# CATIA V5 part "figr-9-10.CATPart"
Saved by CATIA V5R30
Part number: Part1
Bounding box of the stored display mesh (mm): x -15.705 to 98.193, y 0 to 272.268, z -20.723 to 20.723
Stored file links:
  D:\PROJECTS\CATIA V56R 2020\Resources\Parts File\c09_catia_v5_6r2020_prt\figr-9-10.CATPart
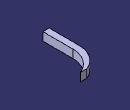
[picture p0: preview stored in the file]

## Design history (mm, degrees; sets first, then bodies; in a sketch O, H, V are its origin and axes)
Body1 (main body)
  Sketch1 on xy-plane, origin (0, 0, 0), H (1, 0, 0), V (0, 1, 0)
    line L1 (0, 0) -> (0, 150)
    arc A1 centre (131.8599, 150) radius 131.8599 from (0, 150) to (82.4884, 272.2681) cw
    length L1 = 150
    tangency: A1 L1
  Sketch2 on zx-plane, origin (0, 0, 0), H (-1, 0, 0), V (0, 0, 1)
    line L1 (15.7048, 20.7231) -> (15.7048, -20.7231)
    line L2 (15.7048, -20.7231) -> (-15.7048, -20.7231)
    line L3 (-15.7048, -20.7231) -> (-15.7048, 20.7231)
    line L4 (-15.7048, 20.7231) -> (15.7048, 20.7231)
    vertical: L1 V, L3 V
    horizontal: L2 H, L4 H
    equidistance: L1 L3 O, L2 L4 O
  Rib1: profile Sketch2, centre curve Sketch1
